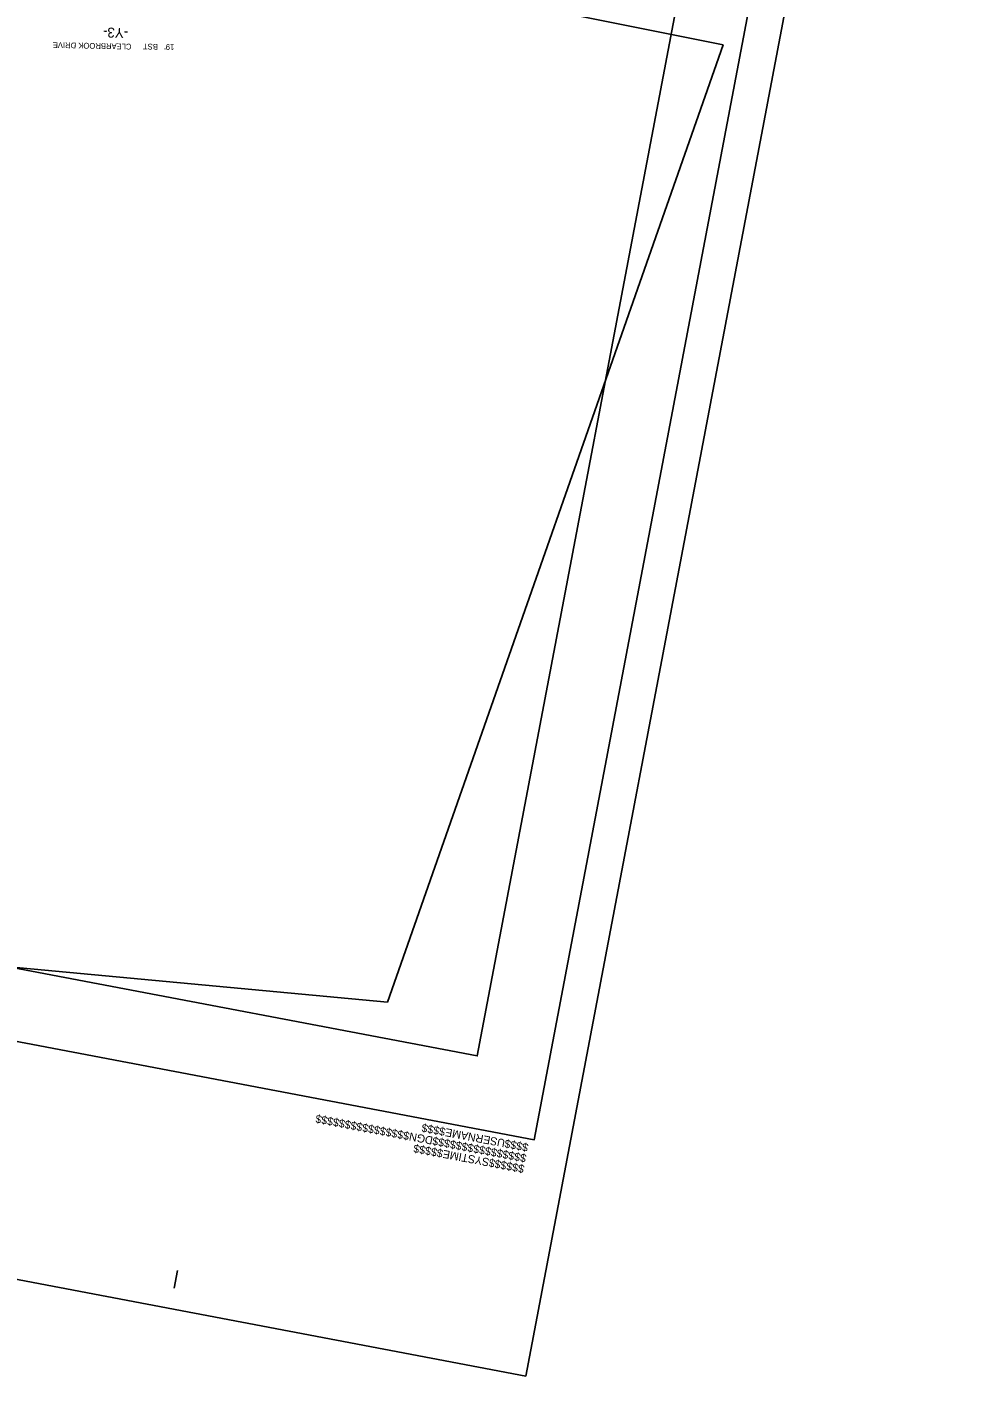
# Model space of a CAD drawing. Extents: x 1615642 to 1617075, y 899305 to 901510.
# Drawn here: x 1616412 to 1617075, y 899305 to 900246 of the extents above; entities that cross this region are included whole.
import ezdxf

# ---------------------------------------------------------------- set-up
doc = ezdxf.new("R2010")
doc.units = 0
for name, color, linetype in [('Default', 7, 'Continuous'), ('DEV BORDER CELL', 7, 'Continuous'), ('Prop Horizontal Alignment Tick Label', 7, 'Continuous'), ('Scratch_Level_0', 7, 'Continuous'), ('Sheet Clip Boundary CELL', 7, 'Continuous'), ('Sheet Plot Border Outside CELL', 7, 'Continuous')]:
    doc.layers.add(name, color=color, linetype=linetype)

msp = doc.modelspace()

# ---------------------------------------------------------------- linework, layer by layer
at = {"layer": 'DEV BORDER CELL'}
for p, q in [((1616766.32, 899469.67), (1616766.32, 899469.67)), ((1616515.11, 899366.21), (1616517.44, 899378.49))]:
    msp.add_line(p, q, dxfattribs=at)
msp.add_lwpolyline([(1616014.55, 901139.21), (1615734.74, 899665.53), (1616766.32, 899469.67), (1617046.12, 900943.35)], close=True, dxfattribs=at)
at = {"layer": 'Scratch_Level_0'}
msp.add_lwpolyline([(1616054.34, 901080.76), (1615793.19, 899705.33), (1616726.52, 899528.12), (1616890.46, 900391.55), (1616774.26, 900413.61), (1616871.48, 900925.61)], close=True, dxfattribs=at)
at = {"layer": 'Sheet Clip Boundary CELL'}
msp.add_lwpolyline([(1616176.29, 901060.7), (1616913.78, 900900.04), (1616896.28, 900812.91), (1616872.94, 900688.21), (1616835.87, 900695.21), (1616753.94, 900262.18), (1616898.09, 900233.43), (1616663.91, 899565.73), (1616252.62, 899604.04), (1615894.68, 899796.73), (1615981.58, 900932.46), (1616145.94, 900899.57)], close=True, dxfattribs=at)
at = {"layer": 'Sheet Plot Border Outside CELL'}
for points in [[(1616760.47, 899304.87), (1615679.78, 899510.06), (1615994.65, 901168.43), (1617075.34, 900963.24)], [(1616760.47, 899304.87), (1617075.34, 900963.24), (1615994.65, 901168.43), (1615679.78, 899510.06)]]:
    msp.add_lwpolyline(points, close=True, dxfattribs=at)

# ---------------------------------------------------------------- texts
at = {"layer": 'Default'}
for s, rotation, p in [('CLEARBROOK DRIVE', 178.75092, (1616485.31, 900234.17)), ("19'   BST", 178.72674, (1616515.15, 900233.83))]:
    msp.add_text(s, height=4, rotation=rotation, dxfattribs=at).set_placement(p)
at = {"layer": 'DEV BORDER CELL'}
for s, p in [('$$$$$$$$$$$$$$$$DGN$$$$$$$$$$$$$$$$', (1616761.22, 899459.32)), ('$$$$USERNAME$$$$', (1616762.63, 899466.77)), ('$$$$$$SYSTIME$$$$$', (1616759.8, 899451.87))]:
    msp.add_text(s, height=5.584, rotation=169.24937, dxfattribs=at).set_placement(p)
at = {"layer": 'Prop Horizontal Alignment Tick Label'}
msp.add_text('-Y3-', height=7, rotation=178.07469, dxfattribs=at).set_placement((1616483.1, 900245.07))

doc.saveas('drawing.dxf')
